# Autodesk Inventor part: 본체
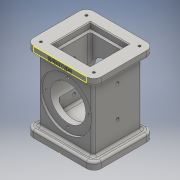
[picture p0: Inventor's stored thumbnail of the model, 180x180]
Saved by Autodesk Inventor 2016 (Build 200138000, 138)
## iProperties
Created: 2017-08
Part Number: 본체
Material: 일반
Document SubType Name: Modeling
Designer: USER
Density: 1 g/cm^3
Appearance: 기본값
Author: USER
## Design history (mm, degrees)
sketch "스케치1"
  geometry: L1 (-46, -41)-(46, -41); L2 (46, -41)-(46, 41); L3 (46, 41)-(-46, 41); L4 (-46, 41)-(-46, -41); L5 (-46, -41)-(46, 41); L6 (46, -41)-(-46, 41); 1 further point
  constraints: 12 end point, 2 midpoint, 2 parallel, 1 horizontal, 1 perpendicular
  dimensions: "d0" = 92 distance of L2.end L3.end; "d1" = 82 distance of L1.end L2.end
extrude "돌출1" new body sketch "스케치1" distance "d2" = 10; taper "d3" = 0 deg
sketch "스케치2"
  geometry: L1 (-46, -41)-(46, -41) reference; L2 (46, -41)-(46, 41) reference; L3 (46, 41)-(-46, 41) reference; L4 (-46, 41)-(-46, -41) reference; L5 (-37, 33)-(37, 33); L6 (37, 33)-(37, -33); L7 (37, -33)-(-37, -33); L8 (-37, -33)-(-37, 33); L9 (-37, 33)-(37, -33); L10 (37, 33)-(-37, -33); 1 further point
  constraints: 12 end point, 2 midpoint, 2 parallel, 1 horizontal, 1 perpendicular
  dimensions: "d4" = 74 distance of L5.start L5.end; "d5" = 66 distance of L5.end L6.end
extrude "돌출2" join sketch "스케치2" distance "d6" = 88; taper "d7" = 0 deg
sketch "스케치3"
  geometry: L1 (46, -41)-(46, 41) reference; L2 (-46, -41)-(46, -41); L3 (46, -41)-(46, 41); L4 (46, 41)-(-46, 41); L5 (-46, 41)-(-46, -41); L6 (-46, -41)-(46, 41); L7 (46, -41)-(-46, 41); 1 further point
  constraints: 12 end point, 2 midpoint, 2 parallel, 1 horizontal, 1 perpendicular
extrude "돌출3" join sketch "스케치3" distance "d8" = 10; taper "d9" = 0 deg
sketch "스케치5"
  geometry: L1 (-9, -10)-(83, -10) reference; L2 (-9, 98)-(83, 98) reference; C1 r 35 at (37, 44); 2 further points
  constraints: 1 centre point, 1 midpoint, 1 vertical alignment
  dimensions: "d10" = 70 diameter of C1; "d11" = 54 distance from line of L1 C1.centre
extrude "돌출4" cut sketch "스케치5" distance "d12" = 3; taper "d13" = 0 deg
sketch "스케치6"
  geometry: C1 r 35 at (0, 0) reference; C2 r 24 at (0, 0); 1 further point
  constraints: 1 centre point, 1 coincident
  dimensions: "d14" = 48 diameter of C2
extrude "돌출5" cut sketch "스케치6" stored distance "d15" = 3; taper "d16" = 0 deg
sketch "스케치7"
  geometry: L1 (24, 24)-(-24, 24); L2 (-24, 24)-(-24, -24); L3 (-24, -24)-(24, -24); L4 (24, -24)-(24, 24); L5 (24, 24)-(-24, -24); L6 (-24, 24)-(24, -24); 1 further point
  constraints: 12 end point, 2 midpoint, 2 parallel, 1 horizontal, 1 perpendicular
  dimensions: "d17" = 48 distance of L2.end L3.end; "d18" = 48 distance of L1.end L2.end
extrude "돌출6" cut sketch "스케치7" distance "d19" = 16; taper "d20" = 0 deg
sketch "스케치8"
  geometry: L1 (-26, 26)-(26, 26); L2 (26, 26)-(26, -26); L3 (26, -26)-(-26, -26); L4 (-26, -26)-(-26, 26); L5 (-26, 26)-(26, -26); L6 (26, 26)-(-26, -26); 1 further point
  constraints: 12 end point, 2 midpoint, 2 parallel, 1 horizontal, 1 perpendicular
  dimensions: "d21" = 52 distance of L1.start L1.end; "d22" = 52 distance of L1.end L2.end
extrude "돌출7" cut sketch "스케치8" distance "d23" = 8; taper "d24" = 0 deg
sketch "스케치9"
  geometry: L1 (-22, 22)-(22, 22); L2 (22, 22)-(22, -22); L3 (22, -22)-(-22, -22); L4 (-22, -22)-(-22, 22); L5 (-22, 22)-(22, -22); L6 (22, 22)-(-22, -22); 1 further point
  constraints: 12 end point, 2 midpoint, 2 parallel, 1 horizontal, 1 perpendicular
  dimensions: "d25" = 44 distance of L1.start L1.end; "d26" = 44 distance of L1.end L2.end
extrude "돌출8" cut sketch "스케치9" distance "d27" = 74; taper "d28" = 0 deg
sketch "스케치10"
  geometry: 5 further points
  constraints: 2 horizontal alignment, 2 vertical alignment
  dimensions: "d29" = 72 distance of point (36, 31) point (-36, 31); "d30" = 36 horizontal distance of point (0, 0) point (-36, 31); "d31" = 62 distance of point (36, -31) point (36, 31); "d32" = 31 vertical distance of point (0, 0) point (36, 31)
hole "구멍1" sketch "스케치10" at (-36, 31), (36, 31), (36, -31), (-36, -31) diameter "d33" = 3.242; stored, may be unused: countersink angle "d37" = 90 deg, drill point angle "d39" = 118 deg; dims "d34" = 4, "d35" = 4, "d36" = 2, "d38" = 6
node "작업 평면1"
sketch "스케치11"
  geometry: C1 r 24 at (0, 0) reference; 2 further points
  constraints: 1 vertical alignment
  dimensions: "d41" = 29 distance of C1.centre point (0, 29)
hole "구멍2" sketch "스케치11" at (0, 29) diameter "d42" = 3.242; stored, may be unused: countersink angle "d46" = 90 deg, drill point angle "d48" = 118 deg; dims "d43" = 4, "d44" = 4, "d45" = 2, "d47" = 6
chamfer "모따기1" distance "d65" = 1; stored, may be unused: second distance "d66" = 2, angle "d67" = 45 deg
chamfer "모따기2" distance "d68" = 1; stored, may be unused: second distance "d69" = 2, angle "d70" = 45 deg
chamfer "모따기3" distance "d71" = 1; stored, may be unused: second distance "d72" = 2, angle "d73" = 45 deg
chamfer "모따기4" distance "d74" = 1; stored, may be unused: second distance "d75" = 2, angle "d76" = 45 deg
fillet "모깎기1" dims "d77" = 10
fillet "모깎기2" dims "d78" = 3
fillet "모깎기3" dims "d79" = 3
fillet "모깎기4" dims "d80" = 3
sketch "스케치14"
  geometry: L1 (72, -7)-(0, -7) reference; L2 (72, 0)-(72, -7) reference; L3 (0, 0)-(72, 0) reference; L4 (0, -7)-(0, 0) reference; 1 further point
sketch "스케치15"
  geometry: L1 (0, 0)-(0, 60) reference; L2 (95, -1)-(95, 61) reference; 4 further points
  constraints: 2 horizontal alignment, 1 midpoint
  dimensions: "d81" = 38 distance from line of L2 point (57, 30); "d82" = 42 distance of point (57, 30) point (15, 30)
hole "구멍4" sketch "스케치15" at (15, 30), (57, 30) diameter "d83" = 4.134; stored, may be unused: countersink angle "d87" = 90 deg, drill point angle "d89" = 118 deg; dims "d84" = 74, "d85" = 4, "d86" = 2, "d88" = 14.2
sketch "스케치16"
  geometry: L1 (0, 0)-(72, 0) reference; L2 (-10, 0)-(-10, -7) reference; 2 further points
  constraints: 1 other
  dimensions: "d90" = 46 distance from line of L2 point (36, -4); "d91" = 4 distance from line of L1 point (36, -4)
feature "엠보싱2" sketch "스케치16" dims "d0" = 92, "d1" = 82, "d92" = 0.5, "d93" = 0
node "솔리드1"
mirror "대칭1"
mirror "대칭2"
pattern_circular "원형 패턴1" dims angle "d50" = 360 deg
mirror "대칭3"
node "투영된 루프1"
other parameters: "d40" = 54
